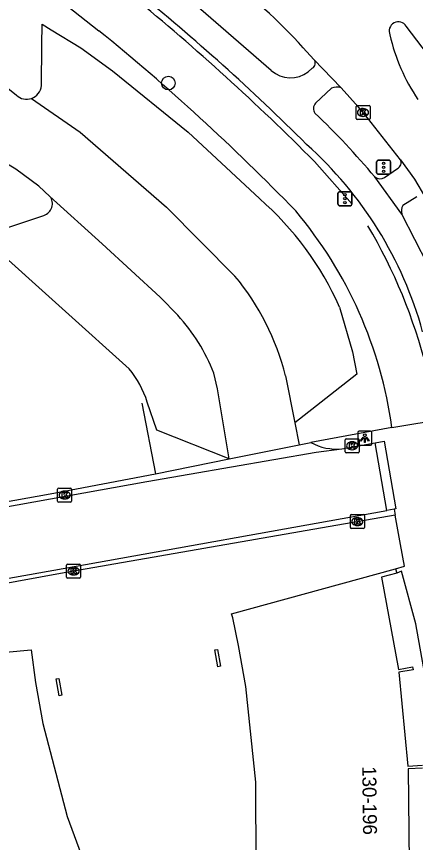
# Model space of a CAD drawing. Extents: x 162880 to 165536, y 384011 to 385179.
# Drawn here: x 164037.6 to 164066.1, y 384395 to 384454 of the extents above; entities that cross this region are included whole.
import ezdxf

# ---------------------------------------------------------------- set-up
doc = ezdxf.new("R2010")
doc.units = 0
for name, color, linetype in [('IMGEO_Boom', 7, 'Continuous'), ('IMGEO_Fietspad_open', 7, 'Continuous'), ('IMGEO_Hek', 7, 'Continuous'), ('IMGEO_Kolk', 7, 'Continuous'), ('IMGEO_Lichtpunt', 7, 'Continuous'), ('IMGEO_Pand', 7, 'Continuous'), ('IMGEO_Pand_nummerreeks', 7, 'Continuous'), ('IMGEO_Parkeervlak_open', 7, 'Continuous'), ('IMGEO_Rijbaan_lokaal_gesloten', 7, 'Continuous'), ('IMGEO_Rijbaan_lokaal_open', 7, 'Continuous'), ('IMGEO_Verkeersregelinstallatiepaal', 7, 'Continuous'), ('IMGEO_Voetpad_open', 7, 'Continuous')]:
    doc.layers.add(name, color=color, linetype=linetype)

msp = doc.modelspace()

# ---------------------------------------------------------------- linework, layer by layer
at = {"layer": 'IMGEO_Boom'}
msp.add_circle((164048.412, 384449.196), 0.489, dxfattribs=at)
at = {"layer": 'IMGEO_Fietspad_open'}
for points in [[(164055.763, 384450.089), (164049.466, 384455.564)], [(164058.705, 384450.27), (164058.419, 384450.012)], [(164058.938, 384447.768), (164060.082, 384448.826)], [(164065.108, 384439.837), (164063.171, 384442.49)], [(164066.968, 384436.228), (164065.108, 384439.837)]]:
    msp.add_lwpolyline(points, dxfattribs=at)
for centre, radius, start, end in [((163944.523, 384330.361), 161.382, 45.17445, 51.02588), ((164058.53, 384450.618), 0.39, 296.70004, 41.91299), ((164057.138, 384451.676), 2.1, 229.09129, 307.58752), ((164060.467, 384448.072), 0.846, 69.72192, 117.03082), ((164059.324, 384447.384), 0.544, 135.215, 217.76169), ((164019.422, 384405.751), 57.129, 40.02246, 46.29652), ((164039.714, 384424.03), 27.88, 15.40667, 48.22393)]:
    msp.add_arc(centre, radius, start, end, dxfattribs=at)
at = {"layer": 'IMGEO_Hek'}
for points in [[(164058.855, 384443.592), (164061.555, 384440.548)], [(164046.515, 384426.338), (164047.482, 384421.288)]]:
    msp.add_lwpolyline(points, dxfattribs=at)
for centre, radius, start, end in [((163938.407, 384323.812), 169.868, 44.84075, 50.75052), ((164029.824, 384419.535), 38.19, 14.07511, 30.6597)]:
    msp.add_arc(centre, radius, start, end, dxfattribs=at)
at = {"layer": 'IMGEO_Kolk'}
for p, q in [((164061.83, 384446.674), (164061.83, 384447.526)), ((164061.905, 384447.6), (164062.757, 384447.6)), ((164062.831, 384447.526), (164062.831, 384446.674)), ((164062.318, 384447.38), (164062.343, 384447.38)), ((164062.757, 384446.6), (164061.905, 384446.6)), ((164062.341, 384446.82), (164062.316, 384446.82)), ((164061.049, 384422.869), (164061.049, 384423.721)), ((164061.124, 384423.795), (164061.976, 384423.795)), ((164061.537, 384423.575), (164061.562, 384423.575)), ((164062.05, 384423.721), (164062.05, 384422.869)), ((164061.976, 384422.795), (164061.124, 384422.795)), ((164061.56, 384423.015), (164061.535, 384423.015)), ((164040.495, 384419.349), (164040.495, 384420.201)), ((164040.57, 384420.275), (164041.422, 384420.275)), ((164040.983, 384420.055), (164041.008, 384420.055)), ((164041.496, 384420.201), (164041.496, 384419.349)), ((164041.422, 384419.275), (164040.57, 384419.275)), ((164041.006, 384419.495), (164040.981, 384419.495)), ((164061.423, 384417.452), (164061.423, 384418.304)), ((164061.498, 384418.378), (164062.35, 384418.378)), ((164061.911, 384418.158), (164061.936, 384418.158)), ((164062.424, 384418.304), (164062.424, 384417.452)), ((164062.35, 384417.378), (164061.498, 384417.378)), ((164061.934, 384417.598), (164061.909, 384417.598)), ((164041.136, 384413.919), (164041.136, 384414.771)), ((164041.211, 384414.845), (164042.063, 384414.845)), ((164041.624, 384414.625), (164041.649, 384414.625)), ((164042.137, 384414.771), (164042.137, 384413.919)), ((164042.063, 384413.845), (164041.211, 384413.845)), ((164041.647, 384414.065), (164041.622, 384414.065))]:
    msp.add_line(p, q, dxfattribs=at)
for points in [[(164061.83, 384446.674), (164061.83, 384447.526)], [(164061.905, 384447.6), (164062.757, 384447.6)], [(164062.831, 384447.526), (164062.831, 384446.674)], [(164062.151, 384447.3), (164062.274, 384447.3), (164062.274, 384447.149), (164062.404, 384447.3), (164062.568, 384447.3), (164062.422, 384447.149), (164062.575, 384446.9), (164062.423, 384446.9), (164062.338, 384447.064), (164062.274, 384446.997), (164062.274, 384446.9), (164062.151, 384446.9), (164062.151, 384447.3)], [(164062.757, 384446.6), (164061.905, 384446.6)], [(164061.049, 384422.869), (164061.049, 384423.721)], [(164061.124, 384423.795), (164061.976, 384423.795)], [(164061.37, 384423.495), (164061.493, 384423.495), (164061.493, 384423.344), (164061.623, 384423.495), (164061.787, 384423.495), (164061.641, 384423.344), (164061.794, 384423.095), (164061.642, 384423.095), (164061.557, 384423.259), (164061.493, 384423.192), (164061.493, 384423.095), (164061.37, 384423.095), (164061.37, 384423.495)], [(164062.05, 384423.721), (164062.05, 384422.869)], [(164061.976, 384422.795), (164061.124, 384422.795)], [(164040.495, 384419.349), (164040.495, 384420.201)], [(164040.57, 384420.275), (164041.422, 384420.275)], [(164040.816, 384419.975), (164040.939, 384419.975), (164040.939, 384419.824), (164041.069, 384419.975), (164041.233, 384419.975), (164041.087, 384419.824), (164041.24, 384419.575), (164041.088, 384419.575), (164041.003, 384419.739), (164040.939, 384419.672), (164040.939, 384419.575), (164040.816, 384419.575), (164040.816, 384419.975)], [(164041.496, 384420.201), (164041.496, 384419.349)], [(164041.422, 384419.275), (164040.57, 384419.275)], [(164061.423, 384417.452), (164061.423, 384418.304)], [(164061.498, 384418.378), (164062.35, 384418.378)], [(164061.744, 384418.078), (164061.867, 384418.078), (164061.867, 384417.927), (164061.997, 384418.078), (164062.161, 384418.078), (164062.015, 384417.927), (164062.168, 384417.678), (164062.016, 384417.678), (164061.931, 384417.842), (164061.867, 384417.775), (164061.867, 384417.678), (164061.744, 384417.678), (164061.744, 384418.078)], [(164062.424, 384418.304), (164062.424, 384417.452)], [(164062.35, 384417.378), (164061.498, 384417.378)], [(164041.136, 384413.919), (164041.136, 384414.771)], [(164041.211, 384414.845), (164042.063, 384414.845)], [(164041.457, 384414.545), (164041.58, 384414.545), (164041.58, 384414.394), (164041.71, 384414.545), (164041.874, 384414.545), (164041.728, 384414.394), (164041.881, 384414.145), (164041.729, 384414.145), (164041.644, 384414.309), (164041.58, 384414.242), (164041.58, 384414.145), (164041.457, 384414.145), (164041.457, 384414.545)], [(164042.137, 384414.771), (164042.137, 384413.919)], [(164042.063, 384413.845), (164041.211, 384413.845)]]:
    msp.add_lwpolyline(points, dxfattribs=at)
for centre, start, end in [((164061.907, 384447.524), 91.55205, 178.44795), ((164061.907, 384447.524), 91.55205, 178.44795), ((164062.755, 384447.524), 1.55205, 88.44795), ((164062.755, 384447.524), 1.55205, 88.44795), ((164061.907, 384446.676), 181.55205, 268.44795), ((164061.907, 384446.676), 181.55205, 268.44795), ((164062.755, 384446.676), 271.55205, 358.44795), ((164062.755, 384446.676), 271.55205, 358.44795), ((164061.126, 384423.719), 91.55205, 178.44795), ((164061.126, 384423.719), 91.55205, 178.44795), ((164061.974, 384423.719), 1.55205, 88.44795), ((164061.974, 384423.719), 1.55205, 88.44795), ((164061.126, 384422.871), 181.55205, 268.44795), ((164061.126, 384422.871), 181.55205, 268.44795), ((164061.974, 384422.871), 271.55205, 358.44795), ((164061.974, 384422.871), 271.55205, 358.44795), ((164040.572, 384420.199), 91.55205, 178.44795), ((164040.572, 384420.199), 91.55205, 178.44795), ((164041.42, 384420.199), 1.55205, 88.44795), ((164041.42, 384420.199), 1.55205, 88.44795), ((164040.572, 384419.351), 181.55205, 268.44795), ((164040.572, 384419.351), 181.55205, 268.44795), ((164041.42, 384419.351), 271.55205, 358.44795), ((164041.42, 384419.351), 271.55205, 358.44795), ((164061.5, 384418.302), 91.55205, 178.44795), ((164061.5, 384418.302), 91.55205, 178.44795), ((164062.348, 384418.302), 1.55205, 88.44795), ((164062.348, 384418.302), 1.55205, 88.44795), ((164061.5, 384417.454), 181.55205, 268.44795), ((164061.5, 384417.454), 181.55205, 268.44795), ((164062.348, 384417.454), 271.55205, 358.44795), ((164062.348, 384417.454), 271.55205, 358.44795), ((164041.213, 384414.769), 91.55205, 178.44795), ((164041.213, 384414.769), 91.55205, 178.44795), ((164042.061, 384414.769), 1.55205, 88.44795), ((164042.061, 384414.769), 1.55205, 88.44795), ((164041.213, 384413.921), 181.55205, 268.44795), ((164041.213, 384413.921), 181.55205, 268.44795), ((164042.061, 384413.921), 271.55205, 358.44795), ((164042.061, 384413.921), 271.55205, 358.44795)]:
    msp.add_arc(centre, 0.0765, start, end, dxfattribs=at)
for centre, major_axis, ratio, start_param, end_param in [((164062.317, 384447.1), (-0.387, 0.002), 0.722429, 4.712389, 7.853982), ((164062.342, 384447.1), (-0.39, 0.002), 0.717154, 1.570796, 4.712389), ((164061.536, 384423.295), (-0.387, 0.002), 0.722429, 4.712389, 7.853982), ((164061.561, 384423.295), (-0.39, 0.002), 0.717154, 1.570796, 4.712389), ((164040.982, 384419.775), (-0.387, 0.002), 0.722429, 4.712389, 7.853982), ((164041.007, 384419.775), (-0.39, 0.002), 0.717154, 1.570796, 4.712389), ((164061.91, 384417.878), (-0.387, 0.002), 0.722429, 4.712389, 7.853982), ((164061.935, 384417.878), (-0.39, 0.002), 0.717154, 1.570796, 4.712389), ((164041.623, 384414.345), (-0.387, 0.002), 0.722429, 4.712389, 7.853982), ((164041.648, 384414.345), (-0.39, 0.002), 0.717154, 1.570796, 4.712389)]:
    msp.add_ellipse(centre, major_axis=major_axis, ratio=ratio, start_param=start_param, end_param=end_param, dxfattribs=at)
at = {"layer": 'IMGEO_Lichtpunt'}
for p, q in [((164061.957, 384424.244), (164061.957, 384423.437)), ((164061.957, 384424.244), (164061.957, 384423.437)), ((164062.859, 384424.339), (164062.051, 384424.339)), ((164062.859, 384424.339), (164062.051, 384424.339)), ((164062.953, 384423.437), (164062.953, 384424.244)), ((164062.953, 384423.437), (164062.953, 384424.244)), ((164062.051, 384423.343), (164062.859, 384423.343)), ((164062.051, 384423.343), (164062.859, 384423.343))]:
    msp.add_line(p, q, dxfattribs=at)
for points in [[(164062.331, 384423.908), (164062.37, 384423.88), (164062.182, 384423.618), (164062.144, 384423.645), (164062.331, 384423.908)], [(164062.433, 384423.86), (164062.48, 384423.86), (164062.48, 384423.538), (164062.433, 384423.538), (164062.433, 384423.86)], [(164062.543, 384423.88), (164062.581, 384423.907), (164062.768, 384423.645), (164062.729, 384423.617), (164062.543, 384423.88)]]:
    msp.add_lwpolyline(points, dxfattribs=at)
msp.add_circle((164062.456, 384424.042), 0.0994, dxfattribs=at)
for centre, start, end in [((164062.051, 384424.244), 90, 180), ((164062.051, 384424.244), 90, 180), ((164062.859, 384424.244), 0, 90), ((164062.859, 384424.244), 0, 90), ((164062.051, 384423.437), 180, 270), ((164062.051, 384423.437), 180, 270), ((164062.859, 384423.437), 270, 0), ((164062.859, 384423.437), 270, 360)]:
    msp.add_arc(centre, 0.0946, start, end, dxfattribs=at)
at = {"layer": 'IMGEO_Pand'}
for points in [[(164054.691, 384393.247), (164054.671, 384399.266), (164053.947, 384406.098), (164053.424, 384409.027), (164053.023, 384411.009), (164052.918, 384411.286), (164064.66, 384414.507)], [(164064.66, 384414.507), (164064.744, 384414.199)], [(164064.744, 384414.199), (164063.644, 384413.901), (164064.86, 384407.325), (164065.874, 384407.501), (164065.908, 384407.303), (164064.894, 384407.127), (164065.544, 384400.416), (164066.572, 384400.477)], [(164030.648, 384393.991), (164028.878, 384400.545), (164027.853, 384400.435), (164027.832, 384400.634), (164028.857, 384400.744), (164028.539, 384402.474), (164027.637, 384407.391), (164026.461, 384407.284), (164026.431, 384407.602), (164038.595, 384408.709), (164038.925, 384406.379), (164039.447, 384403.465), (164041.182, 384396.815), (164043.253, 384391.191)], [(164051.725, 384408.716), (164051.921, 384408.752), (164052.142, 384407.543), (164051.946, 384407.508), (164051.725, 384408.716)], [(164040.387, 384406.646), (164040.584, 384406.682), (164040.805, 384405.473), (164040.608, 384405.437), (164040.387, 384406.646)], [(164066.583, 384400.277), (164065.555, 384400.216), (164065.639, 384393.48), (164066.658, 384393.454)]]:
    msp.add_lwpolyline(points, dxfattribs=at)
at = {"layer": 'IMGEO_Parkeervlak_open'}
for points in [[(164039.337, 384449.019), (164039.374, 384451.894), (164039.394, 384453.395), (164040.027, 384453.009), (164042.148, 384451.714), (164044.409, 384450.076), (164049.821, 384445.688), (164054.936, 384440.945)], [(164045.603, 384428.787), (164041.066, 384432.884), (164035.057, 384438.267), (164039.517, 384439.751)], [(164060.658, 384433.187), (164061.585, 384430.012), (164061.888, 384428.416), (164057.461, 384424.925)], [(164052.768, 384422.357), (164047.577, 384424.413), (164046.907, 384426.418)]]:
    msp.add_lwpolyline(points, dxfattribs=at)
for centre, radius, start, end in [((164038.272, 384449.114), 1.069, 289.23005, 354.91601), ((164039.238, 384440.587), 0.882, 288.47407, 36.20825), ((164040.267, 384424.136), 22.309, 23.93388, 48.88822), ((164040.226, 384424.284), 7.013, 17.71468, 39.9459)]:
    msp.add_arc(centre, radius, start, end, dxfattribs=at)
at = {"layer": 'IMGEO_Rijbaan_lokaal_gesloten'}
for points in [[(164070.136, 384447.077), (164065.415, 384453.259)], [(164058.82, 384450.879), (164058.044, 384451.723)], [(164060.76, 384448.866), (164058.82, 384450.879)], [(164065.011, 384443.726), (164062.653, 384446.715), (164062.008, 384447.48), (164060.76, 384448.866)], [(164065.011, 384443.726), (164066.01, 384442.333), (164066.794, 384441.011)]]:
    msp.add_lwpolyline(points, dxfattribs=at)
for centre, radius, start, end in [((164031.266, 384427.672), 35.993, 41.9299, 54.3762), ((164064.855, 384452.913), 0.658, 31.69908, 204.12267), ((164077.607, 384455.673), 13.692, 192.77945, 213.93501)]:
    msp.add_arc(centre, radius, start, end, dxfattribs=at)
at = {"layer": 'IMGEO_Rijbaan_lokaal_open'}
for points in [[(164035.57, 384449.907), (164037.555, 384448.323)], [(164038.624, 384448.104), (164042.107, 384445.702), (164048.285, 384440.339), (164053.169, 384435.415)], [(164039.949, 384441.108), (164039.156, 384441.824), (164037.513, 384443.06), (164035.999, 384443.924), (164033.71, 384443.608), (164026.677, 384440.034), (164023.715, 384438.629)], [(164049.079, 384432.62), (164047.831, 384433.896), (164043.676, 384437.706), (164039.949, 384441.108)], [(164052.768, 384422.357), (164051.934, 384427.358), (164051.67, 384428.479)], [(164056.794, 384428.279), (164057.461, 384424.925)], [(164057.461, 384424.925), (164057.775, 384423.37)], [(164052.768, 384422.357), (164057.775, 384423.37)], [(164057.775, 384423.37), (164058.592, 384423.535)], [(164060.807, 384423.081), (164063.207, 384423.506)], [(164064.04, 384418.678), (164063.207, 384423.506)], [(164007.341, 384413.643), (164007.908, 384413.755), (164046.862, 384420.743), (164058.972, 384422.832), (164060.807, 384423.081)], [(164027.075, 384417.572), (164032.62, 384418.561), (164039.958, 384419.871), (164047.482, 384421.288), (164052.768, 384422.357)], [(164011.299, 384409.249), (164020.848, 384410.967), (164021.733, 384411.121), (164040.901, 384414.528), (164064.04, 384418.678)], [(164064.546, 384418.769), (164064.04, 384418.678)], [(164064.546, 384418.769), (164064.62, 384418.336)], [(164064.62, 384418.336), (164040.968, 384414.225), (164021.81, 384410.711)]]:
    msp.add_lwpolyline(points, dxfattribs=at)
for centre, radius, start, end in [((164038.274, 384449.115), 1.069, 227.74789, 289.09677), ((164039.366, 384423.914), 17.966, 14.05945, 39.80057), ((164039.119, 384423.507), 13.5, 21.61089, 42.45707), ((164060.408, 384426.766), 3.707, 240.65934, 276.17413)]:
    msp.add_arc(centre, radius, start, end, dxfattribs=at)
at = {"layer": 'IMGEO_Verkeersregelinstallatiepaal'}
for p, q in [((164063.3, 384442.784), (164063.3, 384443.584)), ((164063.3, 384443.584), (164063.3, 384442.784)), ((164063.4, 384443.684), (164064.19, 384443.684)), ((164064.19, 384443.684), (164063.4, 384443.684)), ((164064.29, 384443.584), (164064.29, 384442.784)), ((164064.29, 384442.784), (164064.29, 384443.584)), ((164064.19, 384442.684), (164063.4, 384442.684)), ((164063.4, 384442.684), (164064.19, 384442.684)), ((164060.535, 384440.541), (164060.535, 384441.341)), ((164060.535, 384441.341), (164060.535, 384440.541)), ((164060.635, 384441.441), (164061.425, 384441.441)), ((164061.425, 384441.441), (164060.635, 384441.441)), ((164061.525, 384441.341), (164061.525, 384440.541)), ((164061.525, 384440.541), (164061.525, 384441.341)), ((164061.425, 384440.441), (164060.635, 384440.441)), ((164060.635, 384440.441), (164061.425, 384440.441))]:
    msp.add_line(p, q, dxfattribs=at)
for centre in [(164063.795, 384443.474), (164063.795, 384443.184), (164063.795, 384442.894), (164061.03, 384441.231), (164061.03, 384440.941), (164061.03, 384440.651)]:
    msp.add_circle(centre, 0.085, dxfattribs=at)
for centre, start, end in [((164063.4, 384443.584), 90, 180), ((164063.4, 384443.584), 90, 180), ((164064.19, 384443.584), 0, 90), ((164064.19, 384443.584), 360, 90), ((164063.4, 384442.784), 180, 270), ((164063.4, 384442.784), 180, 270), ((164064.19, 384442.784), 270, 0), ((164064.19, 384442.784), 270, 0), ((164060.635, 384441.341), 90, 180), ((164060.635, 384441.341), 90, 180), ((164061.425, 384441.341), 0, 90), ((164061.425, 384441.341), 360, 90), ((164060.635, 384440.541), 180, 270), ((164060.635, 384440.541), 180, 270), ((164061.425, 384440.541), 270, 0), ((164061.425, 384440.541), 270, 0)]:
    msp.add_arc(centre, 0.1, start, end, dxfattribs=at)
at = {"layer": 'IMGEO_Voetpad_open'}
for points in [[(164039.027, 384456.439), (164043.439, 384452.938)], [(164063.86, 384442.443), (164064.796, 384443.096)], [(164066.174, 384441.067), (164065.184, 384440.456)], [(164064.4, 384424.602), (164068.28, 384425.24)], [(164064.4, 384424.602), (164058.592, 384423.535)], [(164063.207, 384423.506), (164063.848, 384423.62), (164064.68, 384418.793), (164064.546, 384418.769)], [(164064.66, 384414.507), (164065.291, 384414.696), (164065.007, 384416.237), (164064.62, 384418.336)], [(164072.467, 384374.563), (164072.28, 384375.515), (164071.935, 384377.894), (164066.095, 384410.579), (164065.081, 384414.33), (164064.744, 384414.199)]]:
    msp.add_lwpolyline(points, dxfattribs=at)
for centre, radius, start, end in [((163943.391, 384329.373), 158.99, 44.12535, 51.00358), ((164064.579, 384443.522), 0.478, 297.03763, 25.27592), ((164063.549, 384442.954), 0.598, 230.83108, 301.36417), ((164065.738, 384440.074), 0.673, 145.40035, 200.60031), ((164034.09, 384420.376), 30.603, 7.93682, 40.04796)]:
    msp.add_arc(centre, radius, start, end, dxfattribs=at)

# ---------------------------------------------------------------- texts
at = {"layer": 'IMGEO_Pand_nummerreeks'}
msp.add_text('130-196', height=1, rotation=270.71446, dxfattribs=at).set_placement((164062.272, 384400.405))

doc.saveas('drawing.dxf')
